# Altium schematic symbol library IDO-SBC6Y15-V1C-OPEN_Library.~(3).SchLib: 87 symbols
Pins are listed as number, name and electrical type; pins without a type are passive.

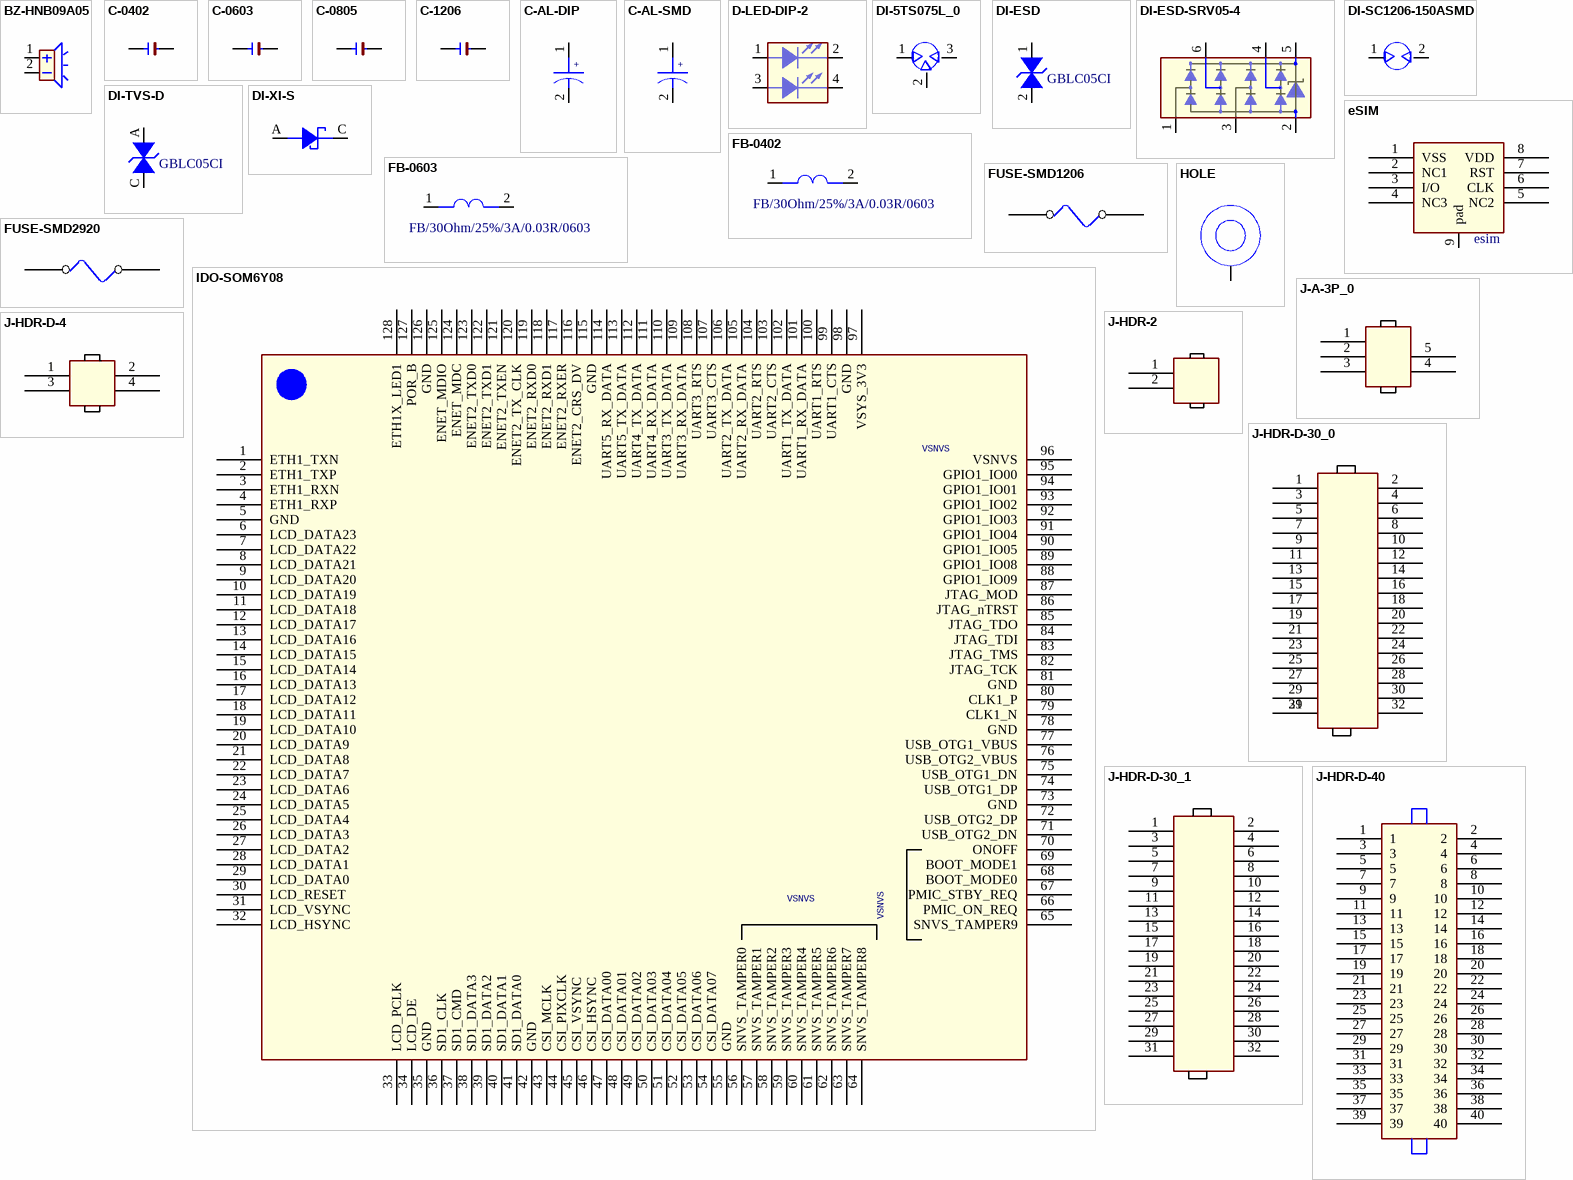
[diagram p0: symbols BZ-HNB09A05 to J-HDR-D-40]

## BZ-HNB09A05
designator BUZZER?
Altium-Right: 20; Altium-Bottom: 30
pins: 1 +, 2 -

## C-0402
designator C?
Altium-Right: 10; Altium-Bottom: 20
footprint 1206
pins: 1, 2

## C-0603
designator C?
Altium-Right: 10; Altium-Bottom: 20
footprint 1206
pins: 1, 2

## C-0805
designator C?
Altium-Right: 10; Altium-Bottom: 20
footprint 1206
pins: 1, 2

## C-1206
designator C?
Altium-Right: 10; Altium-Bottom: 20
footprint 1206
pins: 1, 2

## C-AL-DIP
designator CP?
Altium-Right: 20
pins: 1, 2

## C-AL-SMD
designator CP?
Altium-Right: 20
pins: 1, 2

## D-LED-DIP-2
designator LED?
Altium-Right: 40
pins: 1, 2, 3, 4

## DI-5TS075L_0
designator F?
Altium-Right: 20
pins: 1, 2, 3

## DI-ESD
designator T?, comment GBLC05CI
ESD 0402; Part Number: EB3.1R0UV18402A; Manufacture P/N: MLVG04021R0UV18; Manufacturer: INPAQ; PN Type: Varistor; Altium-Right: 20
pins: 1 I/O2, 2 I/O1

## DI-ESD-SRV05-4
designator D?
Altium-Right: 100; Altium-Bottom: 40
pins: 1, 2, 3, 4, 5, 6

## DI-SC1206-150ASMD
designator F?
Altium-Right: 20; Altium-Bottom: 19
pins: 1, 2

## DI-TVS-D
designator T?, comment GBLC05CI
ESD 0402; Manufacturer: INPAQ; Manufacture P/N: MLVG04021R0UV18; Part Number: EB3.1R0UV18402A; PN Type: Varistor; Altium-Right: 20
pins: A I/O2, C I/O1

## DI-XI-S
designator D?
CLASS: IC; Altium-Right: 30; Altium-Bottom: 20
pins: A, C

## eSIM
designator U?, comment esim
Altium-Right: 60
footprint eSIM
pins: 1 VSS, 2 NC1, 3 I/O, 4 NC3, 5 NC2, 6 CLK, 7 RST, 8 VDD, 9 pad

## FB-0402
designator FB?, comment FB/30Ohm/25%/3A/0.03R/0603
SMD Multilayer Ferrite Chip Bead,3A,30Ohm,0.03R; Part Number: EL4.300Y060300A; Manufacture P/N: PZ1608D300-3R0TF; Manufacture2 P/N: PBY160808T-400Y-N; Manufacturer: SUNLORD; PN Type: SMD FERRITE BEAD; Altium-Right: 40; Altium-Bottom: 20
pins: 1, 2

## FB-0603
designator FB?, comment FB/30Ohm/25%/3A/0.03R/0603
SMD Multilayer Ferrite Chip Bead,3A,30Ohm,0.03R; Manufacturer: SUNLORD; Manufacture2 P/N: PBY160808T-400Y-N; Manufacture P/N: PZ1608D300-3R0TF; Part Number: EL4.300Y060300A; PN Type: SMD FERRITE BEAD; Altium-Right: 40; Altium-Bottom: 20
pins: 1, 2

## FUSE-SMD1206
designator F?
Altium-Right: 30; Altium-Bottom: 20
pins: 1, 2

## FUSE-SMD2920
designator F?
Altium-Right: 30; Altium-Bottom: 20
pins: 1, 2

## HOLE
designator H?  (value not drawn)
Altium-Right: 40
pins: 1

## IDO-SOM6Y08
designator M?
Altium-Right: 510; Altium-Bottom: 470
pins: 1 ETH1_TXN, 2 ETH1_TXP, 3 ETH1_RXN, 4 ETH1_RXP, 5 GND (power), 6 LCD_DATA23, 7 LCD_DATA22, 8 LCD_DATA21, 9 LCD_DATA20, 10 LCD_DATA19, 11 LCD_DATA18, 12 LCD_DATA17, 13 LCD_DATA16, 14 LCD_DATA15, 15 LCD_DATA14, 16 LCD_DATA13, 17 LCD_DATA12, 18 LCD_DATA11, 19 LCD_DATA10, 20 LCD_DATA9, 21 LCD_DATA8, 22 LCD_DATA7, 23 LCD_DATA6, 24 LCD_DATA5, 25 LCD_DATA4, 26 LCD_DATA3, 27 LCD_DATA2, 28 LCD_DATA1, 29 LCD_DATA0, 30 LCD_RESET, 31 LCD_VSYNC, 32 LCD_HSYNC, 33 LCD_PCLK, 34 LCD_DE, 35 GND (power), 36 SD1_CLK, 37 SD1_CMD, 38 SD1_DATA3, 39 SD1_DATA2, 40 SD1_DATA1, 41 SD1_DATA0, 42 GND (power), 43 CSI_MCLK, 44 CSI_PIXCLK, 45 CSI_VSYNC, 46 CSI_HSYNC, 47 CSI_DATA00, 48 CSI_DATA01, 49 CSI_DATA02, 50 CSI_DATA03, 51 CSI_DATA04, 52 CSI_DATA05, 53 CSI_DATA06, 54 CSI_DATA07, 55 GND (power), 56 SNVS_TAMPER0, 57 SNVS_TAMPER1, 58 SNVS_TAMPER2, 59 SNVS_TAMPER3, 60 SNVS_TAMPER4, 61 SNVS_TAMPER5, 62 SNVS_TAMPER6, 63 SNVS_TAMPER7, 64 SNVS_TAMPER8, 65 SNVS_TAMPER9, 66 PMIC_ON_REQ, 67 PMIC_STBY_REQ, 68 BOOT_MODE0, 69 BOOT_MODE1, 70 ONOFF, 71 USB_OTG2_DN, 72 USB_OTG2_DP, 73 GND (power), 74 USB_OTG1_DP, 75 USB_OTG1_DN, 76 USB_OTG2_VBUS, 77 USB_OTG1_VBUS, 78 GND (power), 79 CLK1_N, 80 CLK1_P, 81 GND (power), 82 JTAG_TCK, 83 JTAG_TMS, 84 JTAG_TDI, 85 JTAG_TDO, 86 JTAG_nTRST, 87 JTAG_MOD, 88 GPIO1_IO09, 89 GPIO1_IO08, 90 GPIO1_IO05, 91 GPIO1_IO04, 92 GPIO1_IO03, 93 GPIO1_IO02, 94 GPIO1_IO01, 95 GPIO1_IO00, 96 VSNVS, 97 VSYS_3V3, 98 GND (power), 99 UART1_CTS, 100 UART1_RTS, 101 UART1_RX_DATA, 102 UART1_TX_DATA, 103 UART2_CTS, 104 UART2_RTS, 105 UART2_RX_DATA, 106 UART2_TX_DATA, 107 UART3_CTS, 108 UART3_RTS, 109 UART3_RX_DATA, 110 UART3_TX_DATA, 111 UART4_RX_DATA, 112 UART4_TX_DATA, 113 UART5_TX_DATA, 114 UART5_RX_DATA, 115 GND (power), 116 ENET2_CRS_DV, 117 ENET2_RXER, 118 ENET2_RXD1, 119 ENET2_RXD0, 120 ENET2_TX_CLK, 121 ENET2_TXEN, 122 ENET2_TXD1, 123 ENET2_TXD0, 124 ENET_MDC, 125 ENET_MDIO, 126 GND (power), 127 POR_B, 128 ETH1X_LED1

## J-A-3P_0
designator J?
Altium-Right: 30; Altium-Bottom: 60
pins: 1, 2, 3, 4, 5

## J-HDR-2
designator J?
Altium-Right: 30; Altium-Bottom: 50
pins: 1, 2

## J-HDR-D-4
designator J?
Altium-Right: 30; Altium-Bottom: 50
pins: 1, 2, 3, 4

## J-HDR-D-30_0
designator J?
Altium-Right: 40; Altium-Bottom: 190
pins: 1, 2 16, 3 2, 4 17, 5 3, 6 18, 7 4, 8 19, 9 5, 10 20, 11 6, 12 21, 13 7, 14 22, 15 8, 16 23, 17 9, 18 24, 19 10, 20 25, 21 11, 22 26, 23 12, 24 27, 25 13, 26 28, 27 14, 28 29, 29 15, 29 15, 30, 31, 32

## J-HDR-D-30_1
designator J?
Altium-Right: 40; Altium-Bottom: 190
pins: 1, 2 16, 3 2, 4 17, 5 3, 6 18, 7 4, 8 19, 9 5, 10 20, 11 6, 12 21, 13 7, 14 22, 15 8, 16 23, 17 9, 18 24, 19 10, 20 25, 21 11, 22 26, 23 12, 24 27, 25 13, 26 28, 27 14, 28 29, 29 15, 30, 31, 32

## J-HDR-D-40
designator J?
Altium-Right: 50; Altium-Bottom: 230
pins: 1, 2, 3, 4, 5, 6, 7, 8, 9, 10, 11, 12, 13, 14, 15, 16, 17, 18, 19, 20, 21, 22, 23, 24, 25, 26, 27, 28, 29, 30, 31, 32, 33, 34, 35, 36, 37, 38, 39, 40

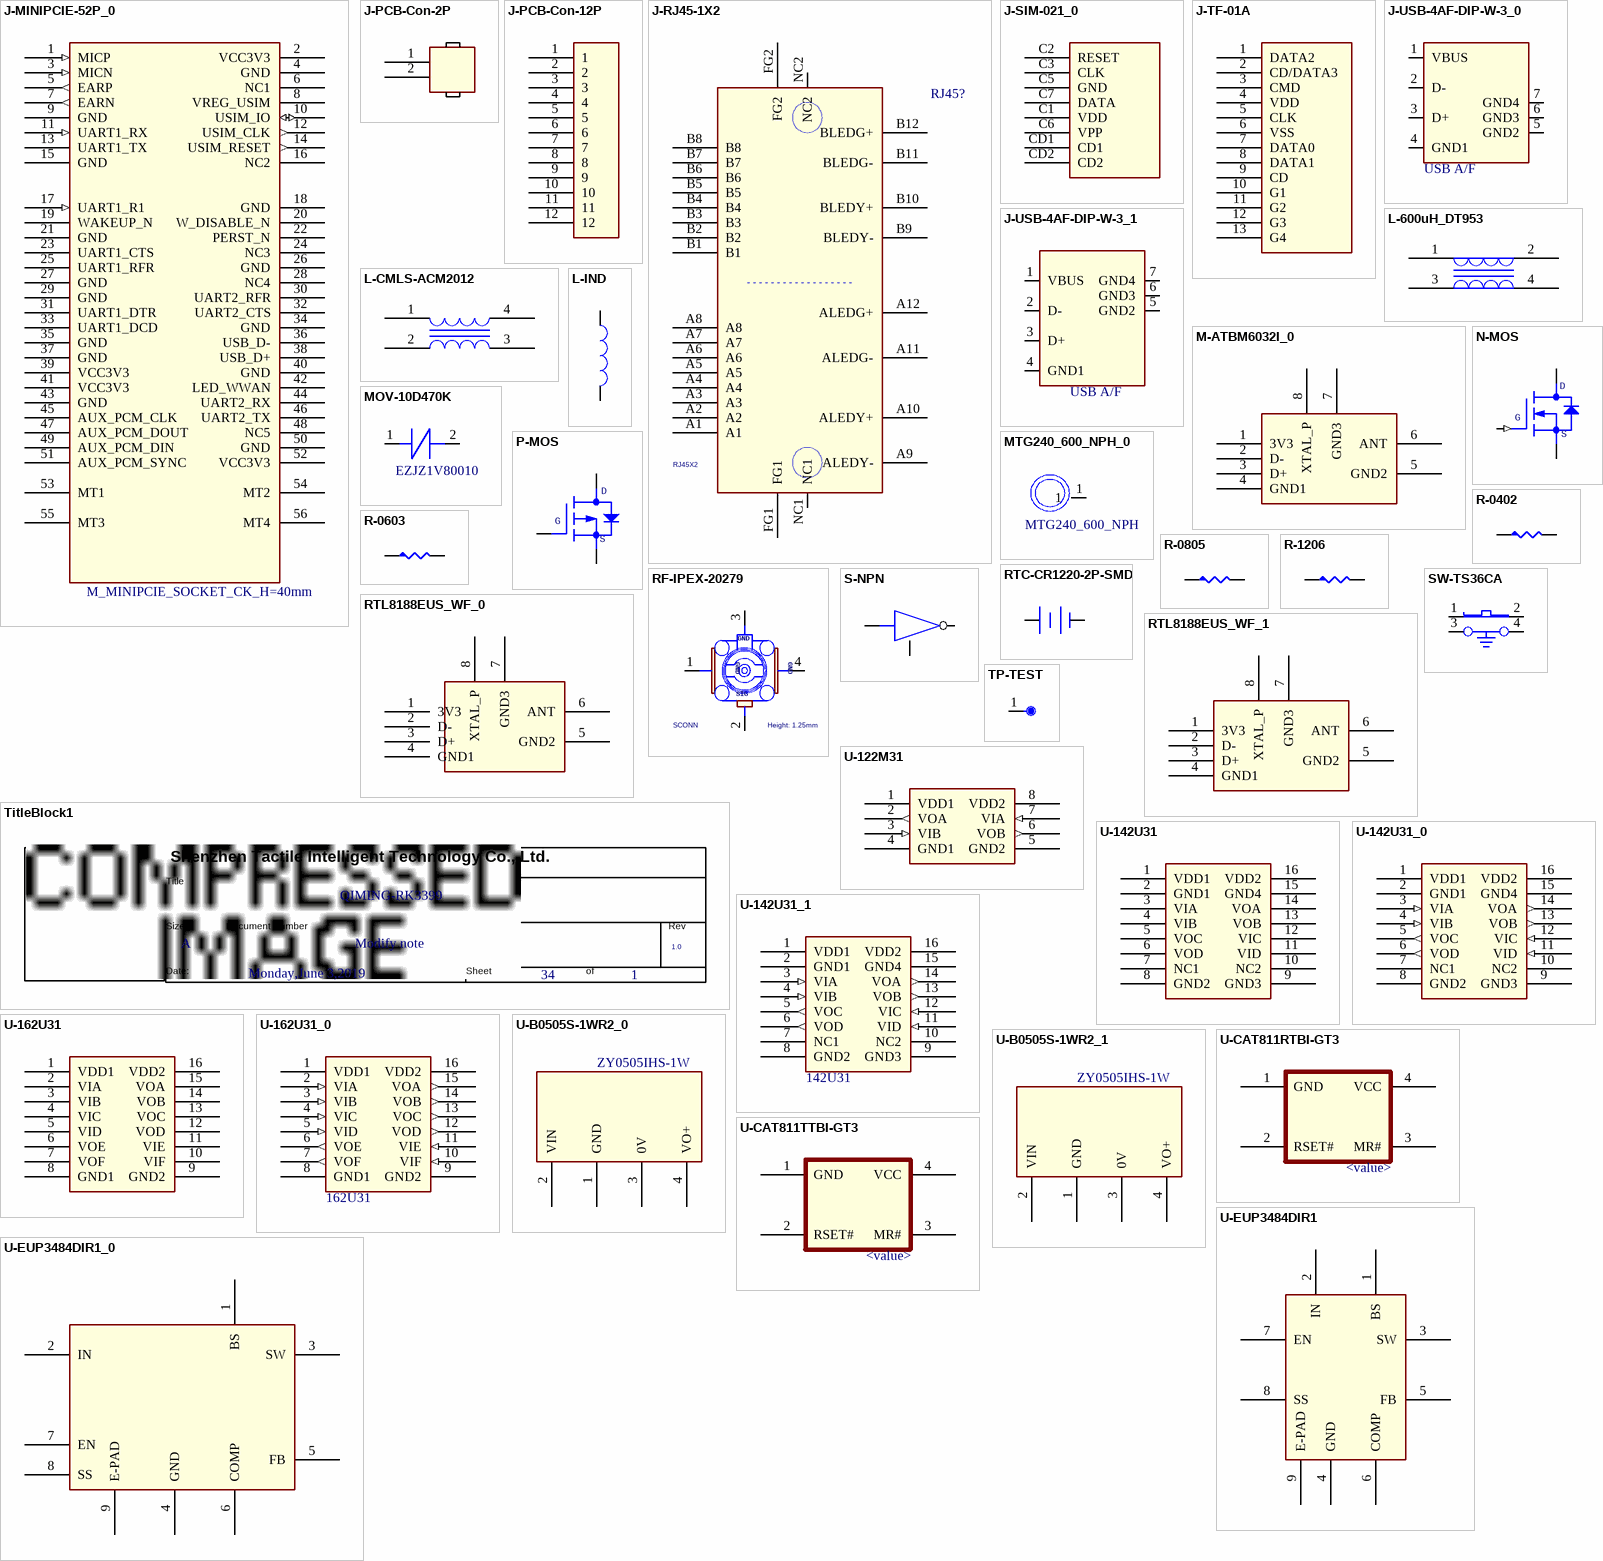
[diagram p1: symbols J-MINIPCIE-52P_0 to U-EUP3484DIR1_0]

## J-MINIPCIE-52P_0
designator MINI-PCIE?, comment M_MINIPCIE_SOCKET_CK_H=40mm
CLASS: IO; Altium-Right: 140; Altium-Bottom: 360
pins: 1 MICP (in), 2 VCC3V3 (power), 3 MICN (in), 4 GND (power), 5 EARP (out), 6 NC1, 7 EARN (out), 8 VREG_USIM (power), 9 GND (power), 10 USIM_IO (io), 11 UART1_RX (in), 12 USIM_CLK (out), 13 UART1_TX, 14 USIM_RESET (out), 15 GND (power), 16 NC2, 17 UART1_R1 (in), 18 GND (power), 19 WAKEUP_N, 20 W_DISABLE_N, 21 GND (power), 22 PERST_N, 23 UART1_CTS, 24 NC3, 25 UART1_RFR, 26 GND (power), 27 GND (power), 28 NC4, 29 GND (power), 30 UART2_RFR, 31 UART1_DTR, 32 UART2_CTS, 33 UART1_DCD, 34 GND (power), 35 GND (power), 36 USB_D-, 37 GND (power), 38 USB_D+, 39 VCC3V3 (power), 40 GND (power), 41 VCC3V3 (power), 42 LED_WWAN, 43 GND (power), 44 UART2_RX, 45 AUX_PCM_CLK, 46 UART2_TX, 47 AUX_PCM_DOUT, 48 NC5, 49 AUX_PCM_DIN, 50 GND (power), 51 AUX_PCM_SYNC, 52 VCC3V3 (power), 53 MT1, 54 MT2, 55 MT3, 56 MT4

## J-PCB-Con-2P
designator J?
Altium-Right: 30; Altium-Bottom: 50
pins: 1, 2

## J-PCB-Con-12P
designator J?
Altium-Right: 30; Altium-Bottom: 130
pins: 1, 2, 3, 4, 5, 6, 7, 8, 9, 10, 11, 12

## J-RJ45-1X2
designator RJ45?, comment RJ45X2
Altium-Right: 110; Altium-Bottom: 270
pins: A1, A2, A3, A4, A5, A6, A7, A8, A9 ALEDY-, A10 ALEDY+, A11 ALEDG-, A12 ALEDG+, B1, B2, B3, B4, B5, B6, B7, B8, B9 BLEDY-, B10 BLEDY+, B11 BLEDG-, B12 BLEDG+, FG1, FG2, NC1, NC2

## J-SIM-021_0
designator J?
Altium-Right: 60; Altium-Bottom: 90
pins: C1 VDD, C2 RESET, C3 CLK, C5 GND, C6 VPP, C7 DATA, CD1, CD2

## J-TF-01A
designator J?
Altium-Right: 60; Altium-Bottom: 140
pins: 1 DATA2, 2 CD/DATA3, 3 CMD, 4 VDD, 5 CLK, 6 VSS, 7 DATA0, 8 DATA1, 9 CD, 10 G1, 11 G2, 12 G3, 13 G4

## J-USB-4AF-DIP-W-3_0
designator USB?, comment USB A/F
micro USB连接器; Altium-Right: 70; Altium-Bottom: 80
pins: 1 VBUS (power), 2 D-, 3 D+, 4 GND1 (power), 5 GND2, 6 GND3, 7 GND4

## J-USB-4AF-DIP-W-3_1
designator USB?, comment USB A/F
micro USB连接器; Altium-Right: 70; Altium-Bottom: 90
pins: 1 VBUS (power), 2 D-, 3 D+, 4 GND1 (power), 5 GND2, 6 GND3, 7 GND4

## L-600uH_DT953
designator CMLP?
Altium-Right: 40; Altium-Bottom: 20
pins: 1, 2, 3, 4

## L-CMLS-ACM2012
designator CMLP?
Altium-Right: 40; Altium-Bottom: 20
pins: 1, 2, 3, 4

## L-IND
designator L?
Altium-Right: 10; Altium-Bottom: 40
pins: 1, 2

## M-ATBM6032I_0
designator M?
Altium-Right: 90; Altium-Bottom: 60
pins: 1 3V3, 2 D-, 3 D+, 4 GND1 (power), 5 GND2 (power), 6 ANT, 7 GND3, 8 XTAL_P

## MOV-10D470K
designator DR?, comment EZJZ1V80010
Altium-Right: 30; Altium-Bottom: 20
pins: 1 A, 2 K

## MTG240_600_NPH_0
designator NPV?, comment MTG240_600_NPH
Altium-Right: 27
pins: 1

## N-MOS
designator Q?
Altium-Right: 50; Altium-Bottom: 40
pins: 1 GATE (in), 2 SOURCE, 3 DRAIN

## P-MOS
designator Q?
Altium-Right: 50; Altium-Bottom: 40
pins: 1 GATE, 2 SOURCE, 3 DRAIN

## R-0402
designator R?
Altium-Right: 20
pins: 1, 2

## R-0603
designator R?
Altium-Right: 20
pins: 1, 2

## R-0805
designator R?
Altium-Right: 20
pins: 1, 2

## R-1206
designator R?
Altium-Right: 20
pins: 1, 2

## RF-IPEX-20279
designator IPEX?  Material: SCONN  Height: 1.25mm
SMD micro Coaxial Connector Receptacle vertial; Pack_Type: MHF-20279; Altium-Right: 60
pins: 1 GND1, 2 SIG, 3 GND2, 4 GND3

## RTC-CR1220-2P-SMD
designator BAT?
Altium-Right: 20
pins: 1 +, 2 -

## RTL8188EUS_WF_0
designator U?
Altium-Right: 90; Altium-Bottom: 60
pins: 1 3V3, 2 D-, 3 D+, 4 GND1 (power), 5 GND2 (power), 6 ANT, 7 GND3, 8 XTAL_P

## RTL8188EUS_WF_1
designator U?
Altium-Right: 90; Altium-Bottom: 60
pins: 1 3V3, 2 D-, 3 D+, 4 GND1 (power), 5 GND2 (power), 6 ANT, 7 GND3, 8 XTAL_P

## S-NPN
designator Q?
Altium-Right: 40; Altium-Bottom: 20
pins: 1, 2, 3

## SW-TS36CA
designator SW?
Altium-Right: 30
pins: 1, 2, 3, 4

## TitleBlock1
designator *  Page Modify Date: Monday,June 3,2019  Doc: Modify note  RevCode: 1.0  Title: QIMING-RK3399  Page Size: A  Page Number: 34  Page Count: 1  (hidden comment: *)  (graphical)
Altium-Right: 455; Altium-Bottom: 91

## TP-TEST
designator TP?
Part Number: CAD; Altium-Right: 10; Altium-Bottom: 20
footprint smd_tp_1mm
pins: 1

## U-122M31
designator U?
Altium-Right: 70; Altium-Bottom: 50
pins: 1 VDD1, 2 VOA (out), 3 VIB (in), 4 GND1, 5 GND2, 6 VOB (out), 7 VIA (in), 8 VDD2

## U-142U31
designator U?
Altium-Right: 70; Altium-Bottom: 90
pins: 1 VDD1, 2 GND1, 3 VIA, 4 VIB, 5 VOC, 6 VOD, 7 NC1, 8 GND2, 9 GND3, 10 NC2, 11 VID, 12 VIC, 13 VOB, 14 VOA, 15 GND4, 16 VDD2

## U-142U31_0
designator U?
Altium-Right: 70; Altium-Bottom: 90
pins: 1 VDD1, 2 GND1, 3 VIA (in), 4 VIB (in), 5 VOC (out), 6 VOD (out), 7 NC1, 8 GND2, 9 GND3, 10 NC2, 11 VID (in), 12 VIC (in), 13 VOB (out), 14 VOA (out), 15 GND4, 16 VDD2

## U-142U31_1
designator U?, comment 142U31
Altium-Right: 70; Altium-Bottom: 90
pins: 1 VDD1, 2 GND1, 3 VIA (in), 4 VIB (in), 5 VOC (out), 6 VOD (out), 7 NC1, 8 GND2, 9 GND3, 10 NC2, 11 VID (in), 12 VIC (in), 13 VOB (out), 14 VOA (out), 15 GND4, 16 VDD2

## U-162U31
designator U?
Altium-Right: 70; Altium-Bottom: 90
pins: 1 VDD1, 2 VIA, 3 VIB, 4 VIC, 5 VID, 6 VOE, 7 VOF, 8 GND1, 9 GND2, 10 VIF, 11 VIE, 12 VOD, 13 VOC, 14 VOB, 15 VOA, 16 VDD2

## U-162U31_0
designator U?, comment 162U31
Altium-Right: 70; Altium-Bottom: 90
pins: 1 VDD1, 2 VIA (in), 3 VIB (in), 4 VIC (in), 5 VID (in), 6 VOE (out), 7 VOF (out), 8 GND1, 9 GND2, 10 VIF (in), 11 VIE (in), 12 VOD (out), 13 VOC (out), 14 VOB (out), 15 VOA (out), 16 VDD2

## U-B0505S-1WR2_0
designator U?, comment ZY0505IHS-1W
Altium-Right: 110; Altium-Bottom: 60
pins: 1 GND, 2 VIN, 3 0V, 4 VO+

## U-B0505S-1WR2_1
designator U?, comment ZY0505IHS-1W
Altium-Right: 110; Altium-Bottom: 60
pins: 1 GND, 2 VIN, 3 0V, 4 VO+

## U-CAT811RTBI-GT3
designator Q?, comment <value>
Altium-Right: 70; Altium-Bottom: 60
pins: 1 GND, 2 RSET# (power), 3 MR#, 4 VCC

## U-CAT811TTBI-GT3
designator Q?, comment <value>
Altium-Right: 70; Altium-Bottom: 60
pins: 1 GND, 2 RSET# (power), 3 MR#, 4 VCC

## U-EUP3484DIR1
designator U?
Altium-Right: 80; Altium-Bottom: 110
pins: 1 BS, 2 IN, 3 SW, 4 GND, 5 FB, 6 COMP, 7 EN, 8 SS, 9 E-PAD

## U-EUP3484DIR1_0
designator U?
Altium-Right: 150; Altium-Bottom: 110
pins: 1 BS, 2 IN, 3 SW, 4 GND, 5 FB, 6 COMP, 7 EN, 8 SS, 9 E-PAD

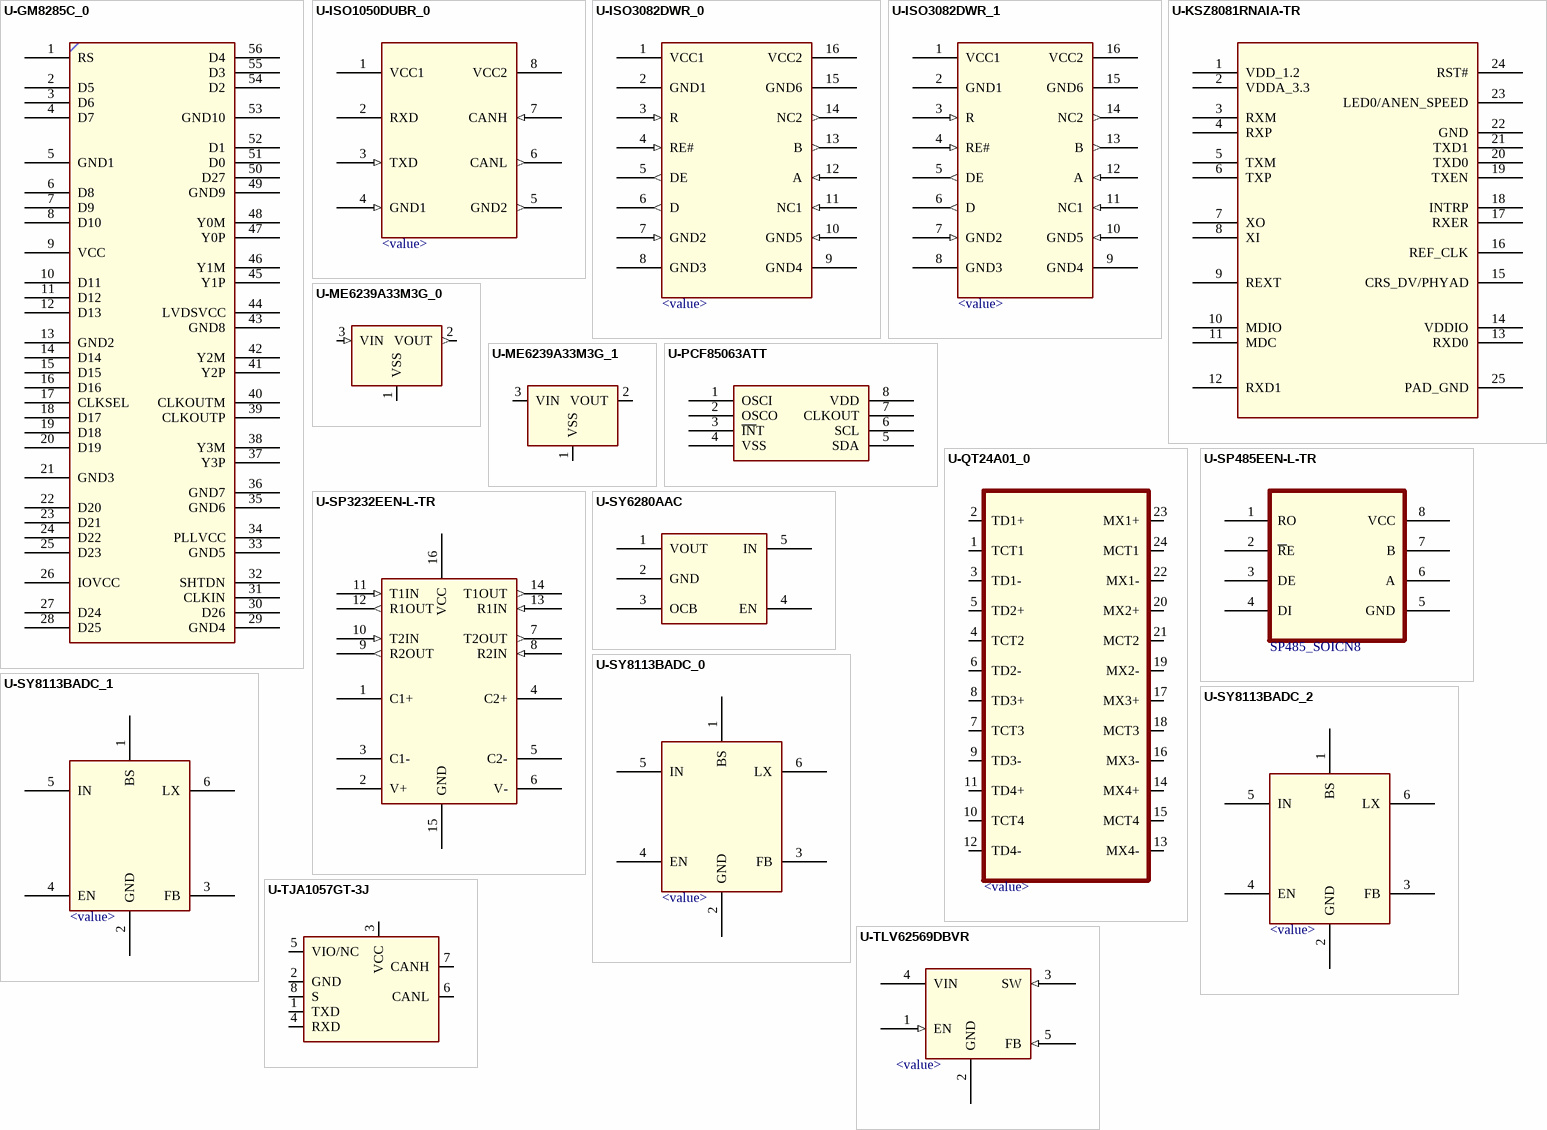
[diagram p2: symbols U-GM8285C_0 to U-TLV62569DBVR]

## U-GM8285C_0
designator U?
Altium-Right: 110; Altium-Bottom: 400
pins: 1 RS, 2 D5, 3 D6, 4 D7, 5 GND1, 6 D8, 7 D9, 8 D10, 9 VCC, 10 D11, 11 D12, 12 D13, 13 GND2, 14 D14, 15 D15, 16 D16, 17 CLKSEL, 18 D17, 19 D18, 20 D19, 21 GND3, 22 D20, 23 D21, 24 D22, 25 D23, 26 IOVCC, 27 D24, 28 D25, 29 GND4, 30 D26, 31 CLKIN, 32 SHTDN, 33 GND5, 34 PLLVCC, 35 GND6, 36 GND7, 37 Y3P, 38 Y3M, 39 CLKOUTP, 40 CLKOUTM, 41 Y2P, 42 Y2M, 43 GND8, 44 LVDSVCC, 45 Y1P, 46 Y1M, 47 Y0P, 48 Y0M, 49 GND9, 50 D27, 51 D0, 52 D1, 53 GND10, 54 D2, 55 D3, 56 D4

## U-ISO1050DUBR_0
designator U?, comment <value>
Altium-Right: 90; Altium-Bottom: 130
pins: 1 VCC1 (power), 2 RXD (power), 3 TXD (in), 4 GND1 (in), 5 GND2 (out), 6 CANL (out), 7 CANH (in), 8 VCC2 (power)

## U-ISO3082DWR_0
designator U?, comment <value>
Altium-Right: 100; Altium-Bottom: 170
pins: 1 VCC1 (power), 2 GND1 (power), 3 R (in), 4 RE# (in), 5 DE (out), 6 D (out), 7 GND2 (in), 8 GND3 (power), 9 GND4 (power), 10 GND5 (in), 11 NC1 (in), 12 A (in), 13 B (out), 14 NC2 (out), 15 GND6 (power), 16 VCC2 (power)

## U-ISO3082DWR_1
designator U?, comment <value>
Altium-Right: 90; Altium-Bottom: 170
pins: 1 VCC1 (power), 2 GND1 (power), 3 R (in), 4 RE# (in), 5 DE (out), 6 D (out), 7 GND2 (in), 8 GND3 (power), 9 GND4 (power), 10 GND5 (in), 11 NC1 (in), 12 A (in), 13 B (out), 14 NC2 (out), 15 GND6 (power), 16 VCC2 (power)

## U-KSZ8081RNAIA-TR
designator U?
CLASS: IC; Altium-Right: 160; Altium-Bottom: 250
pins: 1 VDD_1.2, 2 VDDA_3.3, 3 RXM, 4 RXP, 5 TXM, 6 TXP, 7 XO, 8 XI, 9 REXT, 10 MDIO, 11 MDC, 12 RXD1, 13 RXD0, 14 VDDIO, 15 CRS_DV/PHYAD, 16 REF_CLK, 17 RXER, 18 INTRP, 19 TXEN, 20 TXD0, 21 TXD1, 22 GND, 23 LED0/ANEN_SPEED, 24 RST#, 25 PAD_GND

## U-ME6239A33M3G_0
designator U?
Altium-Right: 60; Altium-Bottom: 40
pins: 1 VSS (power), 2 VOUT (out), 3 VIN (in)

## U-ME6239A33M3G_1
designator U?
Altium-Right: 60; Altium-Bottom: 40
pins: 1 VSS, 2 VOUT, 3 VIN

## U-PCF85063ATT
designator U?
Altium-Right: 90; Altium-Bottom: 50
pins: 1 OSCI, 2 OSCO, 3 ~{IN}T, 4 VSS, 5 SDA, 6 SCL, 7 CLKOUT, 8 VDD

## U-QT24A01_0
designator U?, comment <value>
Altium-Right: 110; Altium-Bottom: 260
pins: 1 TCT1, 2 TD1+, 3 TD1-, 4 TCT2, 5 TD2+, 6 TD2-, 7 TCT3, 8 TD3+, 9 TD3-, 10 TCT4, 11 TD4+, 12 TD4-, 13 MX4-, 14 MX4+, 15 MCT4, 16 MX3-, 17 MX3+, 18 MCT3, 19 MX2-, 20 MX2+, 21 MCT2, 22 MX1-, 23 MX1+, 24 MCT1

## U-SP485EEN-L-TR
designator U?, comment SP485_SOICN8
Altium-Right: 90; Altium-Bottom: 100
pins: 1 RO, 2 ~{R}E, 3 DE, 4 DI, 5 GND, 6 A, 7 B, 8 VCC

## U-SP3232EEN-L-TR
designator U?
Altium-Right: 90; Altium-Bottom: 150
pins: 1 C1+, 2 V+, 3 C1-, 4 C2+, 5 C2-, 6 V-, 7 T2OUT (out), 8 R2IN (in), 9 R2OUT (out), 10 T2IN (in), 11 T1IN (in), 12 R1OUT (out), 13 R1IN (in), 14 T1OUT (out), 15 GND (power), 16 VCC (power)

## U-SY6280AAC
designator U?
Altium-Right: 70; Altium-Bottom: 60
pins: 1 VOUT, 2 GND, 3 OCB, 4 EN, 5 IN

## U-SY8113BADC_0
designator U?, comment <value>
Altium-Right: 80; Altium-Bottom: 100
pins: 1 BS, 2 GND, 3 FB, 4 EN, 5 IN, 6 LX

## U-SY8113BADC_1
designator U?, comment <value>
Altium-Right: 80; Altium-Bottom: 100
pins: 1 BS, 2 GND, 3 FB, 4 EN, 5 IN, 6 LX

## U-SY8113BADC_2
designator U?, comment <value>
Altium-Right: 80; Altium-Bottom: 100
pins: 1 BS, 2 GND, 3 FB, 4 EN, 5 IN, 6 LX

## U-TJA1057GT-3J
designator U?
Altium-Right: 90; Altium-Bottom: 70
pins: 1 TXD, 2 GND (power), 3 VCC (power), 4 RXD, 5 VIO/NC, 6 CANL, 7 CANH, 8 S

## U-TLV62569DBVR
designator U?, comment <value>
Altium-Right: 70; Altium-Bottom: 60
pins: 1 EN (in), 2 GND (power), 3 SW (in), 4 VIN (power), 5 FB (in)

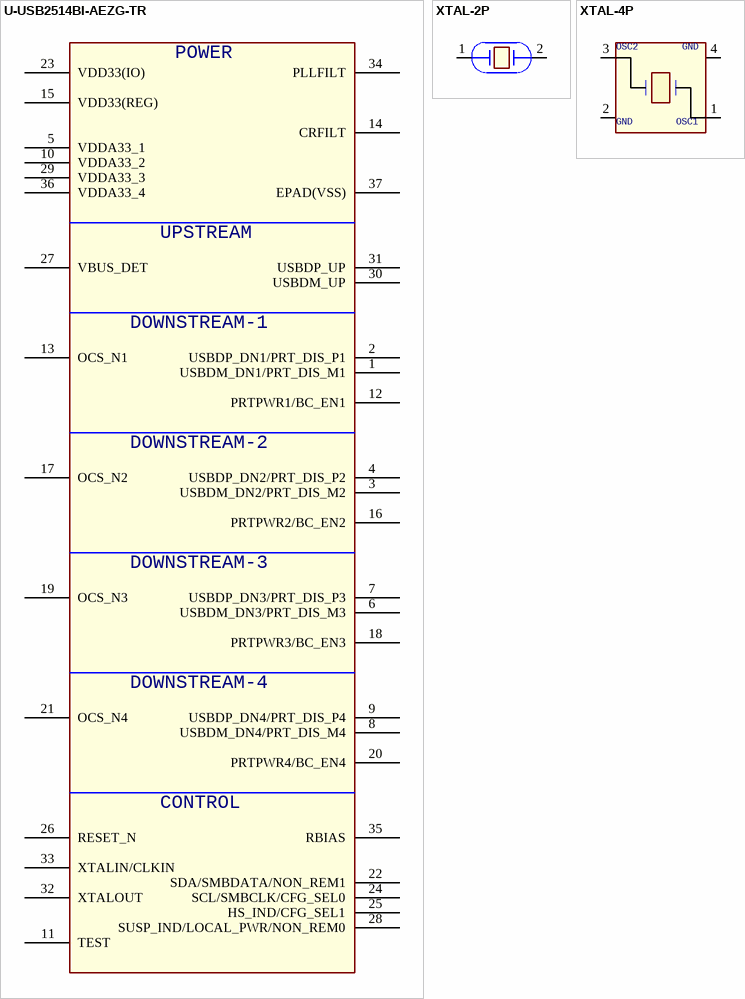
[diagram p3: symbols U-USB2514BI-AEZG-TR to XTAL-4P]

## U-USB2514BI-AEZG-TR
designator U?
Altium-Right: 190; Altium-Bottom: 620
pins: 1 USBDM_DN1/PRT_DIS_M1, 2 USBDP_DN1/PRT_DIS_P1, 3 USBDM_DN2/PRT_DIS_M2, 4 USBDP_DN2/PRT_DIS_P2, 5 VDDA33_1, 6 USBDM_DN3/PRT_DIS_M3, 7 USBDP_DN3/PRT_DIS_P3, 8 USBDM_DN4/PRT_DIS_M4, 9 USBDP_DN4/PRT_DIS_P4, 10 VDDA33_2, 11 TEST, 12 PRTPWR1/BC_EN1, 13 OCS_N1, 14 CRFILT, 15 VDD33(REG), 16 PRTPWR2/BC_EN2, 17 OCS_N2, 18 PRTPWR3/BC_EN3, 19 OCS_N3, 20 PRTPWR4/BC_EN4, 21 OCS_N4, 22 SDA/SMBDATA/NON_REM1, 23 VDD33(IO), 24 SCL/SMBCLK/CFG_SEL0, 25 HS_IND/CFG_SEL1, 26 RESET_N, 27 VBUS_DET, 28 SUSP_IND/LOCAL_PWR/NON_REM0, 29 VDDA33_3, 30 USBDM_UP, 31 USBDP_UP, 32 XTALOUT, 33 XTALIN/CLKIN, 34 PLLFILT, 35 RBIAS, 36 VDDA33_4, 37 EPAD(VSS)

## XTAL-2P
designator XT?
CLASS: IC; Altium-Right: 40; Altium-Bottom: 20
pins: 1, 2

## XTAL-4P
designator XT?
CLASS: IC; Altium-Right: 60
pins: 1, 2, 3, 4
